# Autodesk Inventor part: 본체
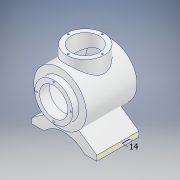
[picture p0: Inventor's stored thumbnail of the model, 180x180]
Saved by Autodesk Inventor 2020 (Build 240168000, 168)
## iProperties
Created: 2023-12
Part Number: 본체
Material: 알루미늄 6061
Document SubType Name: Modeling
Designer: 1강의실14
Density: 2.7 g/cm^3
Appearance: 알루미늄 - 평지
Mass: 1316.41 g
Surface Area: 1070.87 cm^2
Volume: 487.558 cm^3
Author: 1강의실14
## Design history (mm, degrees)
sketch "스케치1"
  geometry: 1 further point
sketch "스케치2"
  geometry: L1 (0, 60)-(0, -60); L2 (27, 60)-(27, 41); L3 (27, 41)-(43, 41); L4 (43, 41)-(43, -43.887); L5 (27, 60)-(36, 60); L6 (36, 60)-(36, 48); L7 (36, 48)-(50, 48); L8 (50, 48)-(50, -48.336); L9 (0, -53)-(0, -60); A1 r 113 centre (0, 53) between (0, -60) and (50, -48.336); A2 r 106 centre (0, 53) between (0, -53) and (43, -43.887); 3 further points
  constraints: 18 end point, 5 perpendicular, 4 point on circle, 2 centre point, 2 vertical, 1 coincident, 1 collinear, 1 horizontal, 1 midpoint, 1 vertical alignment
  dimensions: "d0" = 120 distance of L1.start L1.end; "d2" = 54 diameter of L2 L1; "d3" = 72 diameter of L6 L1; "d4" = 86 diameter of L4 L1; "d5" = 100 diameter of L8 L1; "d7" = 113 radius of A1; "d8" = 7 radial gap between concentric circles of A1 A2; "d9" = 19 distance of L2.start L2.end; "d10" = 41 distance from line of point (0, 0) L3; "d11" = 48 distance from line of L7 point (0, 0)
revolve "회전1" sketch "스케치2" stored, may be unused: angle "d12" = 90 deg
node "작업 평면1"
sketch "스케치3"
  geometry: C1 r 36 at (0, 0); 1 further point
  constraints: 1 centre point, 1 coincident
  dimensions: "d14" = 72 diameter of C1
extrude "돌출1" join sketch "스케치3" stored distance "d15" = 10; taper "d16" = 0 deg
sketch "스케치4"
  geometry: C1 r 27 at (0, 0); 1 further point
  constraints: 1 centre point, 1 coincident
  dimensions: "d17" = 54 diameter of C1
extrude "돌출2" cut sketch "스케치4" stored distance "d18" = 10; taper "d19" = 0 deg; dims "d0" = 120, "d2" = 54, "d3" = 72, "d4" = 86, "d5" = 100, "d7" = 113, "d8" = 7, "d9" = 19, "d10" = 41, "d11" = 48
node "작업 평면2"
sketch "스케치5"
  geometry: L1 (-62, -77)-(-38.5, -77); L2 (-62, -77)-(-62, -67); L3 (-62, -67)-(-16.129, -34.881); L4 (-16.129, -34.881)-(16.129, -34.881); L5 (16.129, -34.881)-(62, -67); L6 (62, -67)-(62, -77); L7 (62, -77)-(38.5, -77); A1 r 52.096 centre (0, -112.096) between (38.5, -77) and (-38.5, -77); A2 r 50 centre (0, 0) between (-26.694, -42.278) and (26.694, -42.278); 5 further points
  constraints: 14 end point, 5 horizontal alignment, 5 point on circle, 3 midpoint, 3 vertical alignment, 2 centre point, 2 equal length, 2 perpendicular, 2 point on line, 1 coincident, 1 horizontal, 1 parallel, 1 vertical
  dimensions: "d21" = 77 distance of L1.end L7.end; "d22" = 10 distance of L5.end L6.end; "d23" = 55 deg angle of L5 L6; "d24" = 17 distance edge to line of A1 L7; "d25" = 77 distance from line of point (0, 0) L7; "d26" = 34.88093 distance from line of point (0, 0) L4; "d27" = 124 distance of L1.start L6.end; "d28" = 100 diameter of A2
extrude "돌출3" join sketch "스케치5" distance "d29" = 80; taper "d30" = 0 deg
sketch "스케치6" dims "d38" = 65
  geometry: L1 (0, 0)-(0, 32.5); 1 further point
  constraints: 2 end point, 1 coincident, 1 vertical, 1 vertical alignment, 2 other
hole "구멍1" sketch "스케치6" at (0, 32.5) diameter "d31" = 3.242; stored, may be unused: countersink angle "d35" = 90 deg, drill point angle "d37" = 118 deg; dims "d32" = 8, "d33" = 4, "d34" = 2, "d36" = 10
sketch "스케치7" dims "d49" = 65
  geometry: L1 (0, 0)-(0, 32.5); 1 further point
  constraints: 2 end point, 1 coincident, 1 vertical, 1 vertical alignment, 2 other
hole "구멍2" sketch "스케치7" at (0, 32.5) diameter "d42" = 3.242; stored, may be unused: countersink angle "d46" = 90 deg, drill point angle "d48" = 118 deg; dims "d43" = 8, "d44" = 4, "d45" = 2, "d47" = 10
node "작업 평면3"
sketch "스케치8"
  geometry: L1 (23.5, 0)-(23.5, -80) reference; L2 (23.5, -61.718)-(13.568, -61.718); L3 (23.5, -47.718)-(13.568, -47.718); L4 (23.5, -47.718)-(23.5, -61.718); A1 r 7 centre (13.568, -54.718) between (13.568, -47.718) and (13.568, -61.718); 1 further point
  constraints: 6 end point, 2 horizontal, 2 point on circle, 2 point on line, 2 tangent, 1 centre point, 1 collinear
  dimensions: "d55" = 14 distance between parallel lines of L3 L2
node "솔리드1"
pattern_circular "원형 패턴1" dims angle "d40" = 360 deg
pattern_circular "원형 패턴2" dims angle "d51" = 360 deg
feature "A9D066F2-1C7D-4E18-AEED-F7BC21143FA4" dims "d31" = 3.242, "d32" = 8, "d33" = 4, "d34" = 2, "d35" = 90 deg, "d36" = 10, "d37" = 118 deg
other parameters: "d13" = 65, "d53" = -6
